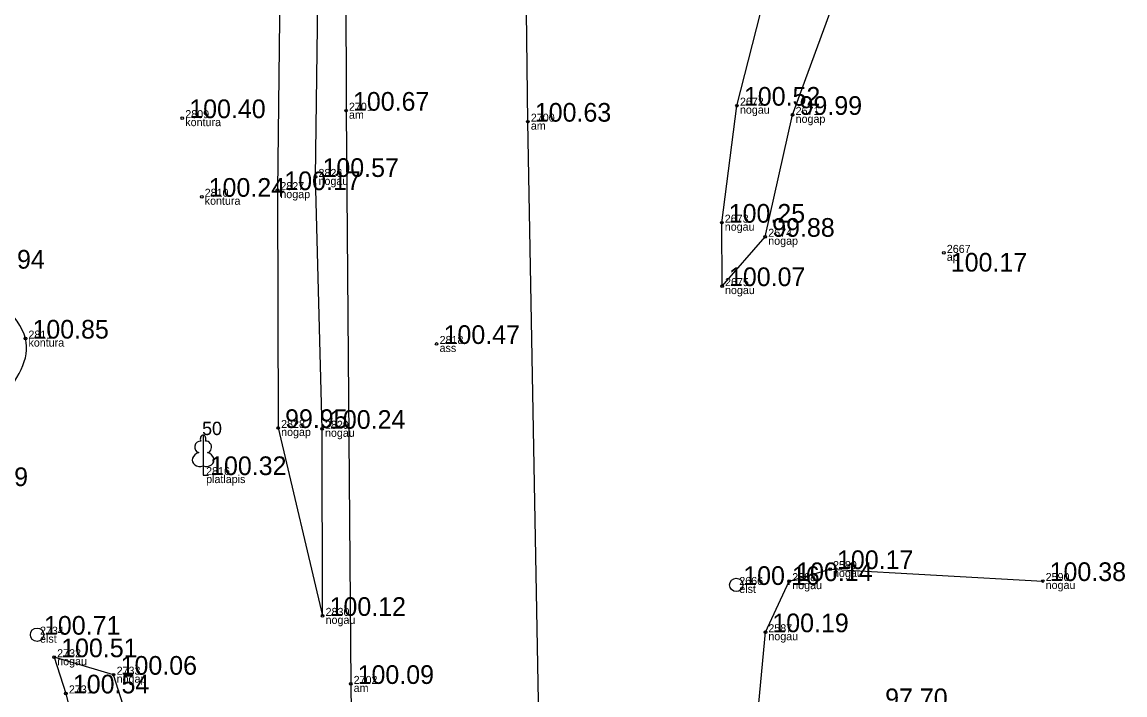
# Model space of a CAD drawing. Extents: x 614911 to 615803, y 262110 to 264311.
# Drawn here: x 615613.61 to 615654.93, y 263784.81 to 263810.02 of the extents above; entities that cross this region are included whole.
import ezdxf

# ---------------------------------------------------------------- set-up
doc = ezdxf.new("R2010")
doc.units = 0
for name, color, linetype in [('Level 1', 7, 'Continuous'), ('Level 18', 7, 'Continuous'), ('Level 21', 7, 'Continuous'), ('Level 31', 7, 'Continuous'), ('Level 37', 7, 'Continuous'), ('Level 53', 7, 'Continuous'), ('Level 54', 7, 'Continuous'), ('Level 57', 7, 'Continuous'), ('Level 58', 7, 'Continuous')]:
    doc.layers.add(name, color=color, linetype=linetype)

msp = doc.modelspace()

# ---------------------------------------------------------------- linework, layer by layer
at = {"layer": 'Level 1'}
for p, q in [((615620.394, 263793.394), (615620.394, 263793.047)), ((615620.394, 263793.047), (615620.594, 263793.047))]:
    msp.add_line(p, q, dxfattribs=at)
for points in [[(615620.394, 263794.547), (615620.394, 263793.394)], [(615620.484, 263794.315), (615620.483, 263794.316)]]:
    msp.add_lwpolyline(points, dxfattribs=at)
for centre, major_axis, ratio, start_param, end_param in [((615620.394, 263794.397), (0, -0.15), 0.707107, 3.14537, 5.287485), ((615620.394, 263794.397), (0, -0.15), 0.707107, 0.995701, 3.137816), ((615620.266, 263794.102), (-0.039, -0.212), 0.861323, 3.141593, 6.283185), ((615620.522, 263794.102), (0.039, -0.212), 0.861323, 0, 3.141593), ((615620.304, 263793.64), (0.307, 0.095), 0.814445, 1.570796, 4.752015), ((615620.484, 263793.64), (-0.307, 0.095), 0.814445, 1.531171, 4.712389)]:
    msp.add_ellipse(centre, major_axis=major_axis, ratio=ratio, start_param=start_param, end_param=end_param, dxfattribs=at)
at = {"layer": 'Level 18'}
for centre in [(615640.372, 263788.931), (615614.17, 263787.067)]:
    msp.add_circle(centre, 0.25, dxfattribs=at)
at = {"layer": 'Level 21'}
msp.add_spline([(615611.338, 263800.783), (615613.737, 263798.162), (615610.71, 263792.635), (615608.354, 263786.496), (615606.328, 263787.946), (615608.992, 263797.312), (615611.338, 263800.783)], degree=3, dxfattribs=at)
at = {"layer": 'Level 31'}
for points in [[(615624.871, 263787.772), (615624.849, 263794.781), (615624.605, 263804.219), (615624.789, 263818.29), (615624.635, 263831.094), (615623.29, 263841.1), (615625.243, 263849.804), (615624.945, 263866.692)], [(615623.452, 263866.152), (615623.941, 263849.846), (615622.267, 263840.775), (615623.243, 263830.979), (615623.356, 263818.692), (615623.176, 263803.724), (615623.204, 263794.812), (615624.871, 263787.772)], [(615639.838, 263800.129), (615639.828, 263802.505), (615640.397, 263806.889), (615642.021, 263813.248), (615643.019, 263815.977), (615645.591, 263821.407), (615646.872, 263827.291), (615648.636, 263833.997)], [(615639.838, 263800.129), (615641.457, 263801.977), (615642.483, 263806.545), (615644.015, 263810.726), (615647.051, 263820.913)], [(615634.983, 263742.124), (615637.151, 263741.18), (615639.129, 263741.365), (615639.417, 263742.418), (615639.55, 263747.26), (615639.824, 263760.15), (615640.622, 263772.665), (615641.102, 263783.306), (615641.462, 263787.159), (615642.356, 263789.074), (615643.885, 263789.526), (615651.852, 263789.078)], [(615614.813, 263786.223), (615615.252, 263784.867), (615616.178, 263781.11), (615615.302, 263777.403), (615613.958, 263774.348), (615616.068, 263766.131), (615618.488, 263761.449), (615618.408, 263755.418), (615617.799, 263750.991), (615617.82, 263744.201), (615617.255, 263741.211)], [(615617.255, 263741.211), (615619.81, 263743.966), (615619.642, 263750.955), (615621.005, 263755.429), (615620.421, 263761.627), (615618.119, 263766.983), (615617.088, 263775.172), (615617.737, 263777.569), (615618.299, 263781.606), (615617.041, 263785.567), (615614.813, 263786.223)]]:
    msp.add_lwpolyline(points, dxfattribs=at)
at = {"layer": 'Level 37'}
for points in [[(615599.876, 263919.455), (615604.05, 263925.447), (615607.684, 263927.303), (615608.393, 263927.682), (615609.17, 263927.713), (615613.447, 263925.367), (615619.425, 263922.192), (615624.751, 263919.238), (615626.516, 263914.529), (615627.589, 263910.62), (615627.021, 263902.326), (615625.968, 263885.28), (615625.441, 263867.412), (615625.701, 263849.423), (615625.695, 263830.774), (615625.747, 263806.701), (615625.922, 263785.222), (615626.06, 263773.355), (615626.048, 263762.098), (615626.08, 263750.419), (615624.574, 263747.097), (615620.445, 263741.787), (615617.245, 263740.487), (615614.217, 263740.593)], [(615633.017, 263781.192), (615632.562, 263806.29), (615632.287, 263829.055), (615632.264, 263849.326), (615632.338, 263865.829), (615632.663, 263885.458)]]:
    msp.add_lwpolyline(points, dxfattribs=at)
at = {"layer": 'Level 57'}
for centre in [(615640.397, 263806.889), (615619.614, 263806.422), (615625.747, 263806.701), (615642.483, 263806.545), (615632.562, 263806.29), (615624.605, 263804.219), (615623.176, 263803.724), (615620.341, 263803.476), (615639.828, 263802.505), (615641.457, 263801.977), (615648.148, 263801.373), (615639.838, 263800.129), (615613.737, 263798.162), (615629.143, 263797.961), (615623.204, 263794.812), (615624.849, 263794.781), (615643.885, 263789.526), (615642.356, 263789.074), (615651.852, 263789.078), (615624.871, 263787.772), (615641.462, 263787.159), (615614.813, 263786.223), (615617.041, 263785.567), (615625.922, 263785.222), (615615.252, 263784.867)]:
    msp.add_circle(centre, 0.05, dxfattribs=at)
at = {"layer": 'Level 58'}
for centre in [(615640.397, 263806.889), (615619.614, 263806.422), (615625.747, 263806.701), (615642.483, 263806.545), (615632.562, 263806.29), (615624.605, 263804.219), (615623.176, 263803.724), (615620.341, 263803.476), (615639.828, 263802.505), (615641.457, 263801.977), (615648.148, 263801.373), (615639.838, 263800.129), (615613.737, 263798.162), (615629.143, 263797.961), (615623.204, 263794.812), (615624.849, 263794.781), (615643.885, 263789.526), (615642.356, 263789.074), (615651.852, 263789.078), (615624.871, 263787.772), (615641.462, 263787.159), (615614.813, 263786.223), (615617.041, 263785.567), (615625.922, 263785.222), (615615.252, 263784.867)]:
    msp.add_circle(centre, 0.05, dxfattribs=at)

# ---------------------------------------------------------------- texts
at = {"layer": 'Level 1'}
msp.add_text(' 50', height=0.5, dxfattribs=at).set_placement((615620.169, 263794.547))
at = {"layer": 'Level 53'}
for s, p in [(' kontura', (615619.614, 263806.122)), (' am', (615625.747, 263806.401)), (' nogau', (615640.397, 263806.589)), (' nogap', (615642.483, 263806.245)), (' am', (615632.562, 263805.99)), (' nogau', (615624.605, 263803.919)), (' nogap', (615623.176, 263803.424)), (' kontura', (615620.341, 263803.176)), (' nogau', (615639.828, 263802.205)), (' nogap', (615641.457, 263801.677)), (' ap', (615648.148, 263801.073)), (' nogau', (615639.838, 263799.829)), (' kontura', (615613.737, 263797.862)), (' ass', (615629.143, 263797.661)), (' nogap', (615623.204, 263794.512)), (' nogau', (615624.849, 263794.481)), (' platlapis', (615620.394, 263792.747)), (' nogau', (615643.885, 263789.226)), (' elst', (615640.372, 263788.631)), (' nogau', (615642.356, 263788.774)), (' nogau', (615651.852, 263788.778)), (' nogau', (615624.871, 263787.472)), (' elst', (615614.17, 263786.767)), (' nogau', (615641.462, 263786.859)), (' nogau', (615614.813, 263785.923)), (' nogap', (615617.041, 263785.267)), (' am', (615625.922, 263784.922))]:
    msp.add_text(s, height=0.3, dxfattribs=at).set_placement(p)
at = {"layer": 'Level 54'}
for s, p in [(' 2701', (615625.747, 263806.701)), (' 2672', (615640.397, 263806.889)), (' 2671', (615642.483, 263806.545)), (' 2809', (615619.614, 263806.422)), (' 2700', (615632.562, 263806.29)), (' 2826', (615624.605, 263804.219)), (' 2827', (615623.176, 263803.724)), (' 2810', (615620.341, 263803.476)), (' 2673', (615639.828, 263802.505)), (' 2674', (615641.457, 263801.977)), (' 2667', (615648.148, 263801.373)), (' 2675', (615639.838, 263800.129)), (' 2811', (615613.737, 263798.162)), (' 2818', (615629.143, 263797.961)), (' 2828', (615623.204, 263794.812)), (' 2829', (615624.849, 263794.781)), (' 2816', (615620.394, 263793.047)), (' 2589', (615643.885, 263789.526)), (' 2666', (615640.372, 263788.931)), (' 2588', (615642.356, 263789.074)), (' 2590', (615651.852, 263789.078)), (' 2830', (615624.871, 263787.772)), (' 2587', (615641.462, 263787.159)), (' 2734', (615614.17, 263787.067)), (' 2732', (615614.813, 263786.223)), (' 2733', (615617.041, 263785.567)), (' 2702', (615625.922, 263785.222)), (' 2731', (615615.252, 263784.867))]:
    msp.add_text(s, height=0.3, dxfattribs=at).set_placement(p)
at = {"layer": 'Level 58'}
for s, p in [(' 100.67', (615625.747, 263806.701)), (' 100.52', (615640.397, 263806.889)), (' 100.40', (615619.614, 263806.422)), (' 100.63', (615632.562, 263806.29)), (' 99.99', (615642.483, 263806.545)), (' 100.57', (615624.605, 263804.219)), (' 100.17', (615623.176, 263803.724)), (' 100.24', (615620.341, 263803.476)), (' 100.25', (615639.828, 263802.505)), (' 99.88', (615641.457, 263801.977)), (' 100.94', (615611.338, 263800.783)), (' 100.17', (615648.148, 263800.673)), (' 100.07', (615639.838, 263800.129)), (' 100.85', (615613.737, 263798.162)), (' 100.47', (615629.143, 263797.961)), (' 99.95', (615623.204, 263794.812)), (' 100.24', (615624.849, 263794.781)), (' 100.32', (615620.394, 263793.047)), (' 100.99', (615610.71, 263792.635)), (' 100.17', (615643.885, 263789.526)), (' 100.16', (615640.372, 263788.931)), (' 100.14', (615642.356, 263789.074)), (' 100.38', (615651.852, 263789.078)), (' 100.12', (615624.871, 263787.772)), (' 100.19', (615641.462, 263787.159)), (' 100.71', (615614.17, 263787.067)), (' 100.51', (615614.813, 263786.223)), (' 100.06', (615617.041, 263785.567)), (' 100.09', (615625.922, 263785.222)), (' 100.54', (615615.252, 263784.867)), (' 97.70', (615645.689, 263784.351))]:
    msp.add_text(s, height=0.7, dxfattribs=at).set_placement(p)

doc.saveas('drawing.dxf')
